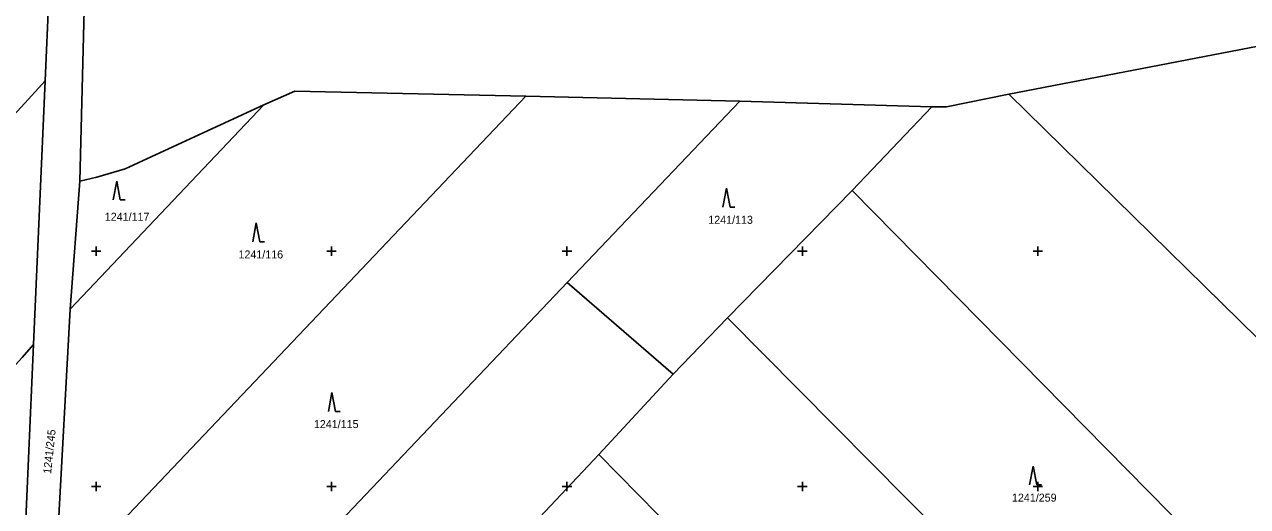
# Model space of a CAD drawing. Extents: x -776734 to -748832, y -1118122 to -976986.
# Drawn here: x -751615.2 to -751355.4, y -1114704.3 to -1114601.8 of the extents above; entities that cross this region are included whole.
import ezdxf

# ---------------------------------------------------------------- set-up
doc = ezdxf.new("R2010")
doc.units = 0
for name, color, linetype in [('KM_Hranice parcel', 7, 'Continuous'), ('KM_Parcelní čísla', 7, 'Continuous'), ('KM_Značky kultur', 7, 'Continuous'), ('Level 61 Křížky', 7, 'Continuous')]:
    doc.layers.add(name, color=color, linetype=linetype)

msp = doc.modelspace()

# ---------------------------------------------------------------- linework, layer by layer
at = {"layer": 'KM_Hranice parcel'}
for p, q in [((-751602.21, -1114585.19), (-751603.5, -1114635.12)), ((-751610.82, -1114613.8), (-751609.62, -1114586.32)), ((-751333.6, -1114602.62), (-751406.13, -1114616.64)), ((-751613.29, -1114669.83), (-751610.82, -1114613.8)), ((-751293.44, -1114727.24), (-751406.13, -1114616.64)), ((-751508.72, -1114617.03), (-751608.83, -1114722.39)), ((-751564.41, -1114618.9), (-751605.57, -1114662.3)), ((-751463.26, -1114618.09), (-751508.72, -1114617.03)), ((-751463.26, -1114618.09), (-751499.96, -1114656.64)), ((-751422.48, -1114619.29), (-751463.26, -1114618.09)), ((-751439.38, -1114637.08), (-751422.48, -1114619.29)), ((-751603.5, -1114635.12), (-751605.57, -1114662.3)), ((-751465.92, -1114664.18), (-751439.38, -1114637.08)), ((-751439.38, -1114637.08), (-751337.18, -1114740.99)), ((-751499.96, -1114656.64), (-751611.61, -1114774.25)), ((-751499.96, -1114656.64), (-751477.44, -1114676.14)), ((-751605.57, -1114662.3), (-751608.83, -1114722.39)), ((-751477.44, -1114676.14), (-751465.92, -1114664.18)), ((-751377.2, -1114753.63), (-751465.92, -1114664.18)), ((-751615.92, -1114729.62), (-751613.29, -1114669.83)), ((-751493.26, -1114693.21), (-751477.44, -1114676.14)), ((-751521.01, -1114722.63), (-751493.26, -1114693.21)), ((-751418.82, -1114768.72), (-751493.26, -1114693.21))]:
    msp.add_line(p, q, dxfattribs=at)
for points in [[(-751855.14, -1114878.92), (-751824.7, -1114845.88), (-751783.59, -1114801.27), (-751766.66, -1114782.9), (-751738.11, -1114751.92), (-751722.27, -1114734.73), (-751704.16, -1114715.09), (-751657.73, -1114664.7), (-751615.2, -1114618.55), (-751610.82, -1114613.8)], [(-751508.72, -1114617.03), (-751557.81, -1114615.99), (-751564.41, -1114618.9)], [(-751406.13, -1114616.64), (-751419.39, -1114619.33), (-751422.48, -1114619.29)], [(-751564.41, -1114618.9), (-751593.88, -1114632.49), (-751599.88, -1114634.24), (-751603.5, -1114635.12)], [(-751806.78, -1114882.34), (-751721.42, -1114788.59), (-751667.32, -1114729.17), (-751615.76, -1114672.55), (-751613.29, -1114669.83)]]:
    msp.add_lwpolyline(points, dxfattribs=at)
at = {"layer": 'KM_Značky kultur'}
for p, q in [((-751595.63, -1114635.1), (-751596.38, -1114639.1)), ((-751594.88, -1114639.1), (-751595.63, -1114635.1)), ((-751466.11, -1114636.62), (-751466.86, -1114640.62)), ((-751465.36, -1114640.62), (-751466.11, -1114636.62)), ((-751594.88, -1114639.1), (-751593.884, -1114639.1)), ((-751465.36, -1114640.62), (-751464.364, -1114640.62)), ((-751565.99, -1114643.98), (-751566.74, -1114647.98)), ((-751565.24, -1114647.98), (-751565.99, -1114643.98)), ((-751565.24, -1114647.98), (-751564.244, -1114647.98)), ((-751549.93, -1114680.03), (-751550.68, -1114684.03)), ((-751549.18, -1114684.03), (-751549.93, -1114680.03)), ((-751549.18, -1114684.03), (-751548.184, -1114684.03)), ((-751400.96, -1114695.66), (-751401.71, -1114699.66)), ((-751400.21, -1114699.66), (-751400.96, -1114695.66)), ((-751400.21, -1114699.66), (-751399.214, -1114699.66))]:
    msp.add_line(p, q, dxfattribs=at)
at = {"layer": 'Level 61 Křížky'}
for p, q in [((-751601, -1114650), (-751599, -1114650)), ((-751600, -1114650), (-751600, -1114649)), ((-751600, -1114651), (-751600, -1114650)), ((-751551, -1114650), (-751549, -1114650)), ((-751550, -1114650), (-751550, -1114649)), ((-751550, -1114651), (-751550, -1114650)), ((-751501, -1114650), (-751499, -1114650)), ((-751500, -1114650), (-751500, -1114649)), ((-751500, -1114651), (-751500, -1114650)), ((-751451, -1114650), (-751449, -1114650)), ((-751450, -1114650), (-751450, -1114649)), ((-751450, -1114651), (-751450, -1114650)), ((-751401, -1114650), (-751399, -1114650)), ((-751400, -1114650), (-751400, -1114649)), ((-751400, -1114651), (-751400, -1114650)), ((-751600, -1114700), (-751600, -1114699)), ((-751550, -1114700), (-751550, -1114699)), ((-751500, -1114700), (-751500, -1114699)), ((-751450, -1114700), (-751450, -1114699)), ((-751400, -1114700), (-751400, -1114699)), ((-751601, -1114700), (-751599, -1114700)), ((-751600, -1114701), (-751600, -1114700)), ((-751551, -1114700), (-751549, -1114700)), ((-751550, -1114701), (-751550, -1114700)), ((-751501, -1114700), (-751499, -1114700)), ((-751500, -1114701), (-751500, -1114700)), ((-751451, -1114700), (-751449, -1114700)), ((-751450, -1114701), (-751450, -1114700)), ((-751401, -1114700), (-751399, -1114700)), ((-751400, -1114701), (-751400, -1114700))]:
    msp.add_line(p, q, dxfattribs=at)

# ---------------------------------------------------------------- texts
at = {"layer": 'KM_Parcelní čísla'}
for s, p in [('1241/117', (-751598.18, -1114643.52)), ('1241/113', (-751469.98, -1114644.17)), ('1241/116', (-751569.78, -1114651.53)), ('1241/115', (-751553.76, -1114687.58)), ('1241/259', (-751405.47, -1114703.21))]:
    msp.add_text(s, height=1.7, dxfattribs=at).set_placement(p)
msp.add_text('1241/245', height=1.7, rotation=84, dxfattribs=at).set_placement((-751609.593, -1114697.376))

doc.saveas('drawing.dxf')
